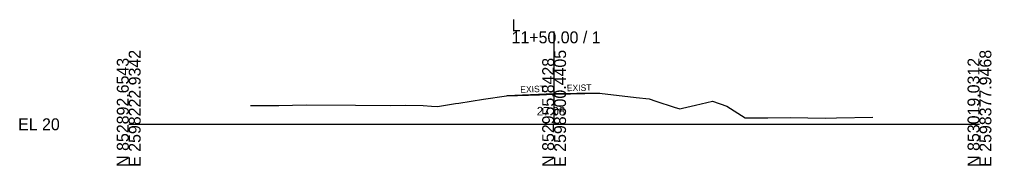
# Model space of a CAD drawing. Extents: x -26 to 1203, y -10 to 9526.
# Drawn here: x -25.7 to 202.8, y 1490.3 to 1524.6 of the extents above; entities that cross this region are included whole.
import ezdxf

# ---------------------------------------------------------------- set-up
doc = ezdxf.new("R2010")
doc.units = 0
for name, color, linetype in [('Exist Cross Section Cell', 7, 'Continuous'), ('Exist XS Center Line Elevation Label', 7, 'Continuous'), ('Exist XS Ground Line', 7, 'Continuous'), ('Prop XS Finish Grade Pavement', 7, 'Continuous'), ('Prop XS SE Text', 7, 'Continuous')]:
    doc.layers.add(name, color=color, linetype=linetype)

msp = doc.modelspace()

# ---------------------------------------------------------------- linework, layer by layer
at = {"layer": 'Exist Cross Section Cell'}
for p, q in [((100, 1500), (100, 1521.83)), ((0, 1500), (100, 1500)), ((100, 1500), (200, 1500))]:
    msp.add_line(p, q, dxfattribs=at)
at = {"layer": 'Exist XS Ground Line'}
for p, q in [((83.37, 1505.94), (88.81, 1506.66)), ((88.81, 1506.66), (96.58, 1506.94)), ((96.58, 1506.94), (99.93, 1507.08)), ((99.93, 1507.08), (103.82, 1507.16)), ((103.82, 1507.16), (110.71, 1507.28)), ((110.71, 1507.28), (119.32, 1506.28)), ((119.32, 1506.28), (122.37, 1505.95)), ((28.62, 1504.45), (35.29, 1504.45)), ((35.29, 1504.45), (41.73, 1504.57)), ((41.73, 1504.57), (53.31, 1504.48)), ((53.31, 1504.48), (61.47, 1504.4)), ((61.47, 1504.4), (65.01, 1504.46)), ((65.01, 1504.46), (69.24, 1504.45)), ((69.24, 1504.45), (71.19, 1504.28)), ((71.19, 1504.28), (72.55, 1504.17)), ((72.55, 1504.17), (76.78, 1504.86)), ((76.78, 1504.86), (77.59, 1505)), ((77.59, 1505), (83.37, 1505.94)), ((122.37, 1505.95), (123.88, 1505.42)), ((123.88, 1505.42), (128.2, 1504.03)), ((128.2, 1504.03), (129.55, 1503.63)), ((129.55, 1503.63), (130.22, 1503.8)), ((130.22, 1503.8), (133.26, 1504.5)), ((133.26, 1504.5), (137.22, 1505.42)), ((137.22, 1505.42), (140.58, 1504.26)), ((140.58, 1504.26), (144.88, 1501.54)), ((144.88, 1501.54), (150.25, 1501.53)), ((150.25, 1501.53), (155.55, 1501.57)), ((155.55, 1501.57), (163.71, 1501.46)), ((163.71, 1501.46), (166.39, 1501.49)), ((166.39, 1501.49), (174.92, 1501.7))]:
    msp.add_line(p, q, dxfattribs=at)
at = {"layer": 'Prop XS Finish Grade Pavement'}
for p, q in [((88.85, 1506.76), (100, 1507.21)), ((100, 1507.21), (110.71, 1507.42))]:
    msp.add_line(p, q, dxfattribs=at)

# ---------------------------------------------------------------- texts
at = {"layer": 'Exist Cross Section Cell'}
for s, p in [('L', (90, 1521.83)), ('11+50.00 / 1', (90, 1519.03)), ('EL 20', (-26, 1498.6))]:
    msp.add_text(s, height=2.8, dxfattribs=at).set_placement(p)
for s, p in [('N 852892.6543', (0, 1490)), ('E 2598222.9342', (2.8, 1490)), ('N 852955.8428', (100, 1490)), ('E 2598300.4405', (102.8, 1490)), ('N 853019.0312', (200, 1490)), ('E 2598377.9468', (202.8, 1490))]:
    msp.add_text(s, height=2.8, rotation=90, dxfattribs=at).set_placement(p)
at = {"layer": 'Exist XS Center Line Elevation Label'}
msp.add_text('27.08', height=2, dxfattribs=at).set_placement((95.93, 1502.08))
at = {"layer": 'Prop XS SE Text'}
for rotation, p in [(2.2906, (92.07, 1507.39)), (1.1458, (103, 1507.77))]:
    msp.add_text('EXIST', height=1.5, rotation=rotation, dxfattribs=at).set_placement(p)

doc.saveas('drawing.dxf')
